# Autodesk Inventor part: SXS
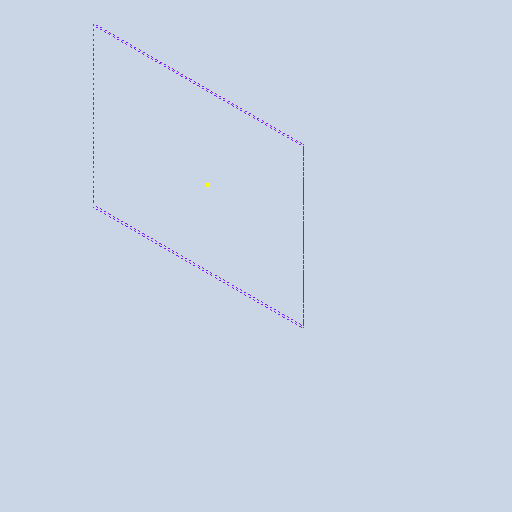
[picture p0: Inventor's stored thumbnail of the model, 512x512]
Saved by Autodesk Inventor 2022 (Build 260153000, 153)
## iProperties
Created: 2022-02
Part Number: SXS
Material: Generic
Document SubType Name: Modeling
Designer: joshw
Density: 1 g/cm^3
Appearance: Default
Author: joshw
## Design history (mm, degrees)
sketch "Sketch1"
  geometry: L1 (-148.007, 104.603)-(122.926, 104.603); L2 (122.926, 104.603)-(122.926, -98.597); L3 (122.926, -98.597)-(-148.007, -98.597); L4 (-148.007, -98.597)-(-148.007, 104.603); 1 further point; 1 other entity
  constraints: 3 other
  node "Image1"
sketch "Sketch3"
  geometry: L1 (-147.4, 106.795)-(122.868, 106.795); L2 (122.868, 106.795)-(122.868, -95.906); L3 (122.868, -95.906)-(-147.4, -95.906); L4 (-147.4, -95.906)-(-147.4, 106.795); 1 further point; 1 other entity
  constraints: 3 other
  node "Image2"
body "Solid1"
